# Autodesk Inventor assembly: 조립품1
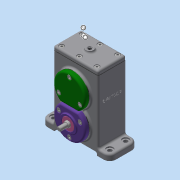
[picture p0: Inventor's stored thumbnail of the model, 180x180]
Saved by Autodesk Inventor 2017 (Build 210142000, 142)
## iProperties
Part Number: 조립품1
Material: 일반
Document SubType Name: Assembly
Designer: mrc
Author: mrc
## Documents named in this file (24)
- C:\Users\mrc\Desktop\600506V1010\조립품1.iam
- C:\Users\mrc\Desktop\600506V1010\개스킷 A.ipt
- C:\Users\mrc\Desktop\600506V1010\개스킷 B.ipt
- C:\Users\mrc\Desktop\600506V1010\개스킷 C.ipt
- C:\Users\mrc\Desktop\600506V1010\베어링 6001.ipt
- 베어링 6001.ipt
- C:\Users\mrc\Desktop\600506V1010\베어링 6002.ipt
- 베어링 6002.ipt
- C:\Users\mrc\Desktop\600506V1010\본체.ipt
- C:\Users\mrc\Desktop\600506V1010\볼트 M4.ipt
- C:\Users\mrc\Desktop\600506V1010\스퍼기어 A.ipt
- C:\Users\mrc\Desktop\600506V1010\스퍼기어 B.ipt
- C:\Users\mrc\Desktop\600506V1010\오일 실 10 20 7.ipt
- C:\Users\mrc\Desktop\600506V1010\오일 실 12 22 7.ipt
- C:\Users\mrc\Desktop\600506V1010\축 A.ipt
- C:\Users\mrc\Desktop\600506V1010\축 B.ipt
- C:\Users\mrc\Desktop\600506V1010\칼라.ipt
- C:\Users\mrc\Desktop\600506V1010\커버 A.ipt
- C:\Users\mrc\Desktop\600506V1010\커버 B.ipt
- C:\Users\mrc\Desktop\600506V1010\커버 C.ipt
- C:\Users\mrc\Desktop\600506V1010\커버 D.ipt
- C:\Users\mrc\Desktop\600506V1010\커버 E.ipt
- C:\Users\mrc\Desktop\600506V1010\키 4 x 4 x 12.ipt
- C:\Users\mrc\Desktop\600506V1010\키 5 x 5 x 12.ipt
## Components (5 placed, 3 different names)
1. 개스킷 A:1
2. 개스킷 B:1
3. 개스킷 C:1
4. 개스킷 B:2
5. 개스킷 B:3
